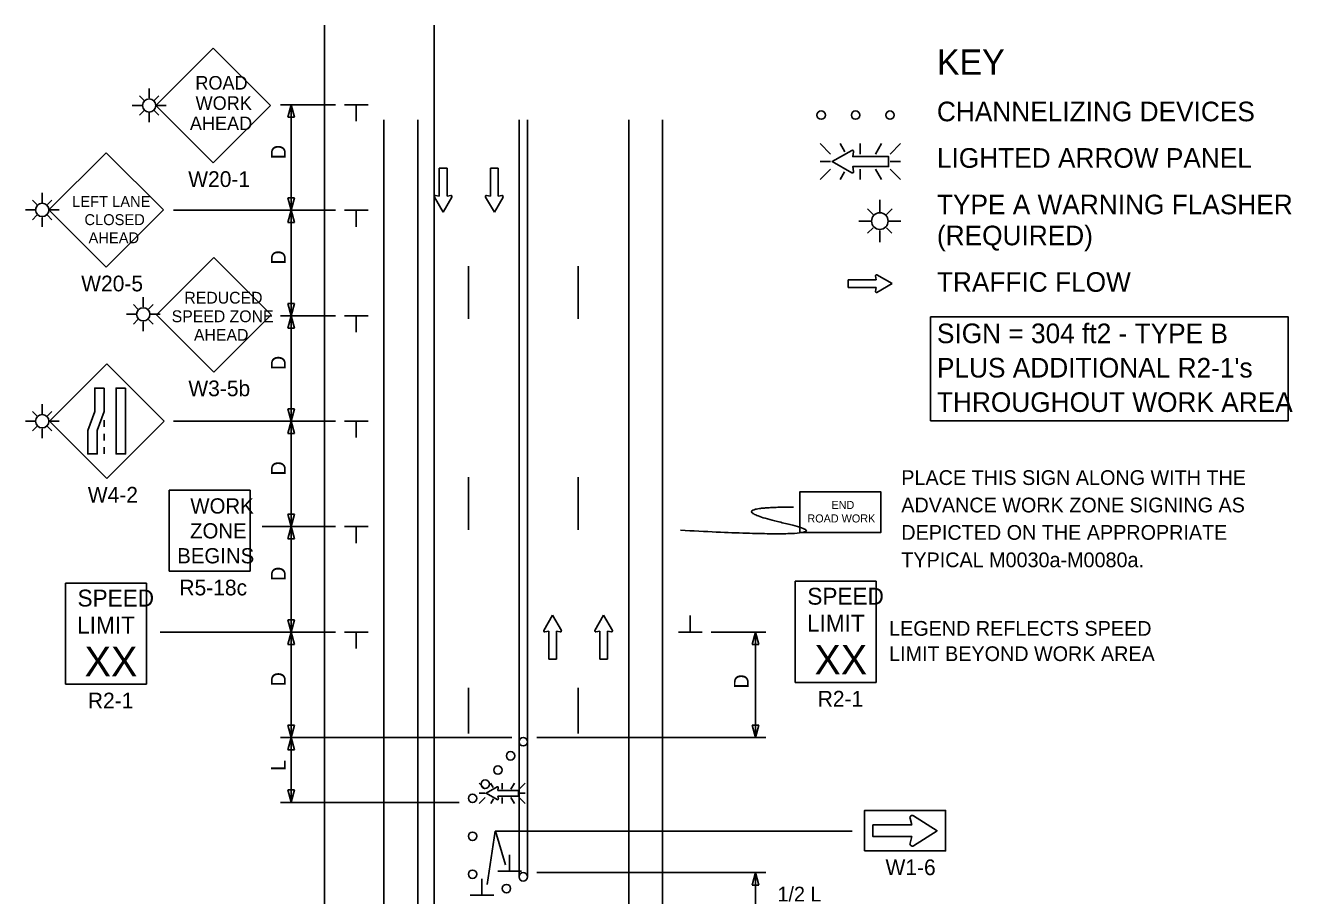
# Model space of a CAD drawing. Extents: x 16473 to 19504, y 4850 to 6919.
# Drawn here: x 16803 to 17404, y 6506 to 6919 of the extents above; entities that cross this region are included whole.
import ezdxf

# ---------------------------------------------------------------- set-up
doc = ezdxf.new("R2010")
doc.units = 0
for name, color, linetype in [('ALI_LEGAL_EX', 7, 'Continuous'), ('MT_SCRATCH_LEVEL_E', 7, 'Continuous'), ('PAVT_EDGE_EX', 7, 'Continuous'), ('TRAFFIC_SIGNS_PR', 7, 'Continuous'), ('TYPICAL_TEXT_DIMEN_EX', 7, 'Continuous'), ('TYPICAL_TEXT_DIMEN_PR', 7, 'Continuous')]:
    doc.layers.add(name, color=color, linetype=linetype)

msp = doc.modelspace()

# ---------------------------------------------------------------- linework, layer by layer
at = {"layer": 'ALI_LEGAL_EX'}
for p, q in [((16945.19, 6918.86), (16945.19, 6067.75)), ((16997.19, 6918.86), (16997.19, 6067.75))]:
    msp.add_line(p, q, dxfattribs=at)
for points in [[(17013.43, 6804.69), (17013.43, 6779.69)], [(17065.43, 6804.69), (17065.43, 6779.69)], [(17013.43, 6704.69), (17013.43, 6679.69)], [(17065.43, 6704.69), (17065.43, 6679.69)], [(17013.43, 6604.69), (17013.43, 6583.06)], [(17065.43, 6604.69), (17065.43, 6583.06)]]:
    msp.add_lwpolyline(points, dxfattribs=at)
at = {"layer": 'MT_SCRATCH_LEVEL_E'}
for p, q in [((17003.35, 6851.09), (16999.61, 6851.09)), ((16999.61, 6851.09), (16999.61, 6837.83)), ((17003.35, 6851.09), (16999.61, 6851.09)), ((16999.61, 6851.09), (16999.61, 6837.83)), ((17003.35, 6837.83), (17003.35, 6851.09)), ((17003.35, 6837.83), (17003.35, 6851.09)), ((17027.58, 6851.09), (17023.84, 6851.09)), ((17023.84, 6851.09), (17023.84, 6837.83)), ((17027.58, 6851.09), (17023.84, 6851.09)), ((17023.84, 6851.09), (17023.84, 6837.83)), ((17027.58, 6837.83), (17027.58, 6851.09)), ((17027.58, 6837.83), (17027.58, 6851.09)), ((16997.35, 6837.46), (17001.5, 6830.22)), ((16997.35, 6837.46), (17001.5, 6830.22)), ((16999.61, 6837.83), (16997.83, 6838.14)), ((16999.61, 6837.83), (16997.83, 6838.14)), ((17001.5, 6830.22), (17005.61, 6837.46)), ((17001.5, 6830.22), (17005.61, 6837.46)), ((17005.13, 6838.14), (17003.35, 6837.83)), ((17005.13, 6838.14), (17003.35, 6837.83)), ((17021.58, 6837.46), (17025.73, 6830.22)), ((17021.58, 6837.46), (17025.73, 6830.22)), ((17023.84, 6837.83), (17022.06, 6838.14)), ((17023.84, 6837.83), (17022.06, 6838.14)), ((17025.73, 6830.22), (17029.84, 6837.46)), ((17025.73, 6830.22), (17029.84, 6837.46)), ((17029.36, 6838.14), (17027.58, 6837.83)), ((17029.36, 6838.14), (17027.58, 6837.83)), ((17206.63, 6798.24), (17193.37, 6798.24)), ((17193.37, 6798.24), (17193.37, 6794.49)), ((17206.63, 6798.24), (17193.37, 6798.24)), ((17193.37, 6798.24), (17193.37, 6794.49)), ((17206.31, 6800.01), (17206.63, 6798.24)), ((17206.31, 6800.01), (17206.63, 6798.24)), ((17214.24, 6796.38), (17207, 6800.49)), ((17214.24, 6796.38), (17207, 6800.49)), ((17193.37, 6794.49), (17206.63, 6794.49)), ((17193.37, 6794.49), (17206.63, 6794.49)), ((17206.63, 6794.49), (17206.31, 6792.72)), ((17206.63, 6794.49), (17206.31, 6792.72)), ((17207, 6792.24), (17214.24, 6796.38)), ((17207, 6792.24), (17214.24, 6796.38)), ((17053.33, 6639.17), (17049.22, 6631.93)), ((17053.33, 6639.17), (17049.22, 6631.93)), ((17057.48, 6631.93), (17053.33, 6639.17)), ((17057.48, 6631.93), (17053.33, 6639.17)), ((17077.52, 6639.17), (17073.41, 6631.93)), ((17077.52, 6639.17), (17073.41, 6631.93)), ((17081.67, 6631.93), (17077.52, 6639.17)), ((17081.67, 6631.93), (17077.52, 6639.17)), ((17049.7, 6631.24), (17051.48, 6631.56)), ((17049.7, 6631.24), (17051.48, 6631.56)), ((17051.48, 6631.56), (17051.48, 6618.3)), ((17051.48, 6631.56), (17051.48, 6618.3)), ((17055.22, 6618.3), (17055.22, 6631.56)), ((17055.22, 6631.56), (17057, 6631.24)), ((17055.22, 6618.3), (17055.22, 6631.56)), ((17055.22, 6631.56), (17057, 6631.24)), ((17073.89, 6631.24), (17075.67, 6631.56)), ((17073.89, 6631.24), (17075.67, 6631.56)), ((17075.67, 6631.56), (17075.67, 6618.3)), ((17075.67, 6631.56), (17075.67, 6618.3)), ((17079.41, 6618.3), (17079.41, 6631.56)), ((17079.41, 6631.56), (17081.19, 6631.24)), ((17079.41, 6618.3), (17079.41, 6631.56)), ((17079.41, 6631.56), (17081.19, 6631.24)), ((17051.48, 6618.3), (17055.22, 6618.3)), ((17051.48, 6618.3), (17055.22, 6618.3)), ((17075.67, 6618.3), (17079.41, 6618.3)), ((17075.67, 6618.3), (17079.41, 6618.3))]:
    msp.add_line(p, q, dxfattribs=at)
for centre, start, end in [((16997.76, 6837.68), 80.03619, 209.77312), ((16997.76, 6837.68), 80.03619, 209.77312), ((17005.2, 6837.68), 330.42484, 99.96381), ((17005.2, 6837.68), 330.42484, 99.96381), ((17021.99, 6837.68), 80.03619, 209.77312), ((17021.99, 6837.68), 80.03619, 209.77312), ((17029.43, 6837.68), 330.42484, 99.96381), ((17029.43, 6837.68), 330.42484, 99.96381), ((17206.77, 6800.09), 60.42484, 189.96381), ((17206.77, 6800.09), 60.42484, 189.96381), ((17206.77, 6792.65), 170.03619, 299.77312), ((17206.77, 6792.65), 170.03619, 299.77312), ((17049.63, 6631.7), 150.42484, 279.96381), ((17049.63, 6631.7), 150.42484, 279.96381), ((17057.07, 6631.7), 260.03619, 29.77312), ((17057.07, 6631.7), 260.03619, 29.77312), ((17073.82, 6631.7), 150.42484, 279.96381), ((17073.82, 6631.7), 150.42484, 279.96381), ((17081.26, 6631.7), 260.03619, 29.77312), ((17081.26, 6631.7), 260.03619, 29.77312)]:
    msp.add_arc(centre, 0.463, start, end, dxfattribs=at)
at = {"layer": 'PAVT_EDGE_EX'}
for p, q in [((16973.43, 6873.99), (16973.43, 6149.2)), ((16989.43, 6873.99), (16989.43, 6149.2)), ((17037.43, 6873.99), (17037.43, 6514.86)), ((17041.43, 6873.99), (17041.43, 6515.67)), ((17089.43, 6873.99), (17089.43, 6149.2)), ((17105.43, 6873.99), (17105.43, 6149.2))]:
    msp.add_line(p, q, dxfattribs=at)
at = {"layer": 'TRAFFIC_SIGNS_PR'}
for p, q in [((16892.52, 6908.05), (16865.33, 6880.86)), ((16919.7, 6880.86), (16892.52, 6908.05)), ((16862.18, 6884.41), (16862.18, 6888.91)), ((16859.66, 6883.37), (16857.56, 6885.48)), ((16864.69, 6883.37), (16866.8, 6885.48)), ((16859.02, 6880.86), (16854.19, 6880.86)), ((16859.66, 6878.35), (16857.56, 6876.24)), ((16862.18, 6872.89), (16862.18, 6877.3)), ((16864.69, 6878.35), (16866.8, 6876.24)), ((16865.33, 6880.86), (16870.21, 6880.86)), ((16865.33, 6880.86), (16892.52, 6853.67)), ((16892.52, 6853.67), (16919.7, 6880.86)), ((16841.8, 6858.48), (16814.64, 6831.32)), ((16868.95, 6831.32), (16841.8, 6858.48)), ((17180.05, 6862.77), (17184.98, 6857.84)), ((17191.81, 6858.95), (17189.6, 6862.77)), ((17199.13, 6857.84), (17199.13, 6862.77)), ((17206.37, 6857.84), (17209.22, 6862.77)), ((17213.28, 6857.84), (17218.22, 6862.77)), ((17184.98, 6854.28), (17180.05, 6854.28)), ((17213.28, 6854.28), (17218.22, 6854.28)), ((17180.05, 6845.79), (17184.98, 6850.72)), ((17189.56, 6845.79), (17191.67, 6849.45)), ((17199.13, 6850.72), (17199.13, 6845.79)), ((17209.26, 6845.79), (17206.41, 6850.72)), ((17213.28, 6850.72), (17218.22, 6845.79)), ((16808.98, 6833.84), (16806.87, 6835.94)), ((16811.49, 6834.88), (16811.49, 6839.38)), ((16814, 6833.84), (16816.11, 6835.94)), ((17208.39, 6830.49), (17208.39, 6836.11)), ((16808.34, 6831.32), (16803.5, 6831.32)), ((16808.98, 6828.81), (16806.87, 6826.7)), ((16814, 6828.81), (16816.11, 6826.7)), ((16814.64, 6831.32), (16819.53, 6831.32)), ((16814.64, 6831.32), (16841.8, 6804.17)), ((16841.8, 6804.17), (16868.95, 6831.32)), ((17205.25, 6829.19), (17202.62, 6831.82)), ((17211.52, 6829.19), (17214.16, 6831.82)), ((16811.49, 6823.36), (16811.49, 6827.77)), ((17204.45, 6826.05), (17198.41, 6826.05)), ((17205.25, 6822.91), (17202.62, 6820.28)), ((17211.52, 6822.91), (17214.15, 6820.28)), ((17212.32, 6826.05), (17218.42, 6826.05)), ((17208.39, 6816.1), (17208.39, 6821.61)), ((16892.79, 6808.76), (16865.64, 6781.6)), ((16919.94, 6781.6), (16892.79, 6808.76)), ((16856.86, 6784.35), (16854.76, 6786.46)), ((16859.38, 6785.4), (16859.38, 6789.9)), ((16861.89, 6784.35), (16864, 6786.46)), ((16856.22, 6781.84), (16851.39, 6781.84)), ((16862.53, 6781.84), (16867.41, 6781.84)), ((16865.64, 6781.6), (16892.79, 6754.45)), ((16892.79, 6754.45), (16919.94, 6781.6)), ((16856.86, 6779.33), (16854.76, 6777.22)), ((16859.38, 6773.87), (16859.38, 6778.29)), ((16861.89, 6779.33), (16864, 6777.22)), ((16842.14, 6758.31), (16814.98, 6731.16)), ((16869.29, 6731.16), (16842.14, 6758.31)), ((16811.49, 6734.71), (16811.49, 6739.21)), ((16808.98, 6733.66), (16806.87, 6735.77)), ((16814, 6733.66), (16816.11, 6735.77)), ((16808.34, 6731.15), (16803.5, 6731.15)), ((16808.97, 6728.64), (16806.87, 6726.53)), ((16811.49, 6723.19), (16811.49, 6727.6)), ((16814, 6728.64), (16816.11, 6726.53)), ((16814.64, 6731.15), (16819.53, 6731.15)), ((16814.98, 6731.16), (16842.14, 6704.01)), ((16840.89, 6731.65), (16840.89, 6728.45)), ((16842.14, 6704.01), (16869.29, 6731.16)), ((16840.89, 6725.25), (16840.89, 6722.05)), ((16840.89, 6718.85), (16840.89, 6715.65)), ((16871.68, 6660.01), (16871.68, 6698.41)), ((16871.68, 6698.41), (16910.08, 6698.41)), ((16910.08, 6660.01), (16910.08, 6698.41)), ((16871.68, 6660.01), (16910.08, 6660.01)), ((16822.45, 6654.44), (16860.85, 6654.44)), ((16822.45, 6606.44), (16822.45, 6654.44)), ((16860.85, 6606.44), (16860.85, 6654.44)), ((17168.28, 6655.31), (17206.68, 6655.31)), ((17168.28, 6607.31), (17168.28, 6655.31)), ((17206.68, 6607.31), (17206.68, 6655.31)), ((16822.45, 6606.44), (16860.85, 6606.44)), ((17168.28, 6607.31), (17206.68, 6607.31)), ((17018.55, 6559.58), (17021.37, 6556.76)), ((17023.98, 6559.58), (17025.19, 6557.49)), ((17029.45, 6556.76), (17029.45, 6559.58)), ((17035.24, 6559.58), (17033.61, 6556.76)), ((17037.54, 6556.76), (17040.36, 6559.58)), ((17021.37, 6554.73), (17018.55, 6554.73)), ((17018.55, 6549.88), (17021.37, 6552.7)), ((17025.27, 6552.06), (17024.01, 6549.88)), ((17029.45, 6552.7), (17029.45, 6549.88)), ((17033.59, 6552.7), (17035.21, 6549.88)), ((17037.54, 6554.73), (17040.36, 6554.73)), ((17037.54, 6552.7), (17040.36, 6549.88)), ((17205.15, 6539.78), (17223.55, 6539.78)), ((17205.15, 6539.78), (17205.15, 6534.18)), ((17223.55, 6539.78), (17222.71, 6542.84)), ((17224.39, 6544.08), (17235.55, 6536.98)), ((17223.55, 6534.18), (17205.15, 6534.18)), ((17222.71, 6531.12), (17223.55, 6534.18)), ((17235.55, 6536.98), (17224.39, 6529.88))]:
    msp.add_line(p, q, dxfattribs=at)
for points in [[(17195.06, 6859.56), (17185.77, 6854.28), (17195.06, 6848.96)], [(17195.93, 6849.59), (17195.53, 6851.85), (17212.55, 6851.85), (17212.55, 6856.65), (17195.53, 6856.65), (17195.94, 6858.94)], [(17027.12, 6551.72), (17021.81, 6554.73), (17027.12, 6557.77)], [(17027.62, 6557.41), (17027.4, 6556.12), (17037.12, 6556.12), (17037.12, 6553.37), (17027.4, 6553.37), (17027.63, 6552.07)], [(17222.71, 6542.84), (17223.55, 6539.78), (17205.15, 6539.78), (17205.15, 6534.18), (17223.55, 6534.18), (17222.71, 6531.12)], [(17224.39, 6529.88), (17235.55, 6536.98), (17224.39, 6544.08)]]:
    msp.add_lwpolyline(points, dxfattribs=at)
for points in [[(16840.89, 6746.9), (16840.89, 6735.72), (16837.54, 6726.83), (16837.54, 6715.65), (16833.05, 6715.65), (16833.05, 6726.83), (16836.39, 6735.72), (16836.39, 6746.9)], [(16851.02, 6746.9), (16851.02, 6715.65), (16846.53, 6715.65), (16846.53, 6746.9)], [(17170.47, 6678.4), (17208.87, 6678.4), (17208.87, 6697.6), (17170.47, 6697.6)], [(17201.15, 6527.38), (17239.55, 6527.38), (17239.55, 6546.58), (17201.15, 6546.58)]]:
    msp.add_lwpolyline(points, close=True, dxfattribs=at)
for centre, radius in [((16862.18, 6880.86), 3.15), ((17180.61, 6876.31), 2), ((17196.91, 6876.31), 2), ((17213.21, 6876.31), 2), ((16811.49, 6831.32), 3.15), ((17208.39, 6826.05), 3.94), ((16859.38, 6781.84), 3.15), ((16811.49, 6731.15), 3.15), ((17039.43, 6579.2), 2), ((17033.43, 6572.48), 2), ((17027.43, 6565.77), 2), ((17021.43, 6559.06), 2), ((17015.43, 6552.35), 2), ((17015.43, 6534.35), 2), ((17015.43, 6534.35), 2), ((17015.43, 6516.35), 2), ((17039.43, 6515.11), 2), ((17031.43, 6509.53), 2)]:
    msp.add_circle(centre, radius, dxfattribs=at)
for centre, radius, start, end in [((17195.35, 6859.03), 0.598, 350.73078, 118.89165), ((17195.34, 6849.48), 0.597, 241.48329, 9.95933), ((17027.29, 6557.47), 0.341, 350.04067, 118.51671), ((17027.29, 6552.02), 0.341, 241.10835, 9.26922), ((17223.79, 6543.14), 1.12, 57.53038, 195.32692), ((17223.79, 6543.14), 1.12, 57.53038, 195.32692), ((17223.79, 6530.82), 1.12, 164.67308, 302.46962), ((17223.79, 6530.82), 1.12, 164.67308, 302.46963)]:
    msp.add_arc(centre, radius, start, end, dxfattribs=at)
msp.add_open_spline([(17167.51, 6690.42), (17129.72, 6690.42), (17197.74, 6674.95), (17113.94, 6679.44)], degree=2, dxfattribs=at)
at = {"layer": 'TYPICAL_TEXT_DIMEN_EX'}
msp.add_lwpolyline([(17232.44, 6780.57), (17401.89, 6780.57), (17401.89, 6731.37), (17232.44, 6731.37)], close=True, dxfattribs=at)
at = {"layer": 'TYPICAL_TEXT_DIMEN_PR'}
for p, q in [((16924.43, 6881.18), (16950.43, 6881.18)), ((16927.86, 6875.32), (16929.43, 6881.18)), ((16929.43, 6831.18), (16929.43, 6881.18)), ((16929.43, 6881.18), (16931, 6875.32)), ((16954.68, 6881.18), (16965.93, 6881.18)), ((16960.31, 6881.18), (16960.31, 6873.39)), ((16929.43, 6875.32), (16927.86, 6875.32)), ((16931, 6875.32), (16929.43, 6875.32)), ((16929.43, 6831.18), (16927.86, 6837.04)), ((16927.86, 6837.04), (16929.43, 6837.04)), ((16929.43, 6837.04), (16931, 6837.04)), ((16931, 6837.04), (16929.43, 6831.18)), ((16873.63, 6831.18), (16950.43, 6831.18)), ((16924.43, 6831.18), (16950.43, 6831.18)), ((16927.86, 6825.32), (16929.43, 6831.18)), ((16929.43, 6781.18), (16929.43, 6831.18)), ((16929.43, 6831.18), (16931, 6825.32)), ((16954.68, 6831.18), (16965.93, 6831.18)), ((16960.31, 6831.18), (16960.31, 6823.39)), ((16929.43, 6825.32), (16927.86, 6825.32)), ((16931, 6825.32), (16929.43, 6825.32)), ((16929.43, 6781.18), (16927.86, 6787.04)), ((16927.86, 6787.04), (16929.43, 6787.04)), ((16929.43, 6787.04), (16931, 6787.04)), ((16931, 6787.04), (16929.43, 6781.18)), ((16924.43, 6781.18), (16950.43, 6781.18)), ((16924.43, 6781.18), (16950.43, 6781.18)), ((16927.86, 6775.32), (16929.43, 6781.18)), ((16929.43, 6781.18), (16931, 6775.32)), ((16929.43, 6731.18), (16929.43, 6781.18)), ((16954.68, 6781.18), (16965.93, 6781.18)), ((16960.31, 6781.18), (16960.31, 6773.39)), ((16929.43, 6775.32), (16927.86, 6775.32)), ((16931, 6775.32), (16929.43, 6775.32)), ((16929.43, 6731.18), (16927.86, 6737.04)), ((16927.86, 6737.04), (16929.43, 6737.04)), ((16929.43, 6737.04), (16931, 6737.04)), ((16931, 6737.04), (16929.43, 6731.18)), ((16873.63, 6731.18), (16950.43, 6731.18)), ((16927.86, 6725.32), (16929.43, 6731.18)), ((16929.43, 6681.7), (16929.43, 6731.7)), ((16929.43, 6731.18), (16931, 6725.32)), ((16954.68, 6731.18), (16965.93, 6731.18)), ((16960.31, 6731.18), (16960.31, 6723.39)), ((16929.43, 6725.32), (16927.86, 6725.32)), ((16931, 6725.32), (16929.43, 6725.32)), ((16929.43, 6681.18), (16927.86, 6687.04)), ((16927.86, 6687.04), (16929.43, 6687.04)), ((16929.43, 6687.04), (16931, 6687.04)), ((16931, 6687.04), (16929.43, 6681.18)), ((16915.75, 6681.18), (16950.43, 6681.18)), ((16927.86, 6675.32), (16929.43, 6681.18)), ((16929.43, 6631.18), (16929.43, 6681.18)), ((16929.43, 6681.18), (16931, 6675.32)), ((16954.68, 6681.18), (16965.93, 6681.18)), ((16960.31, 6681.18), (16960.31, 6673.39)), ((16929.43, 6675.32), (16927.86, 6675.32)), ((16931, 6675.32), (16929.43, 6675.32)), ((16929.43, 6631.18), (16927.86, 6637.04)), ((16927.86, 6637.04), (16929.43, 6637.04)), ((16929.43, 6637.04), (16931, 6637.04)), ((16931, 6637.04), (16929.43, 6631.18)), ((17118.56, 6631.18), (17118.56, 6638.96)), ((16867.31, 6631.18), (16950.43, 6631.18)), ((16927.86, 6625.32), (16929.43, 6631.18)), ((16929.43, 6631.18), (16929.43, 6581.18)), ((16929.43, 6631.18), (16931, 6625.32)), ((16954.68, 6631.18), (16965.93, 6631.18)), ((16960.31, 6631.18), (16960.31, 6623.39)), ((17124.18, 6631.18), (17112.93, 6631.18)), ((17154.43, 6631.18), (17128.43, 6631.18)), ((17147.86, 6625.32), (17149.43, 6631.18)), ((17149.43, 6631.18), (17151, 6625.32)), ((17149.43, 6631.18), (17149.43, 6581.18)), ((16929.43, 6625.32), (16927.86, 6625.32)), ((16931, 6625.32), (16929.43, 6625.32)), ((17149.43, 6625.32), (17147.86, 6625.32)), ((17151, 6625.32), (17149.43, 6625.32)), ((16929.43, 6581.18), (16927.86, 6587.04)), ((16927.86, 6587.04), (16929.43, 6587.04)), ((16929.43, 6587.04), (16931, 6587.04)), ((16931, 6587.04), (16929.43, 6581.18)), ((17149.43, 6581.18), (17147.86, 6587.04)), ((17147.86, 6587.04), (17149.43, 6587.04)), ((17149.43, 6587.04), (17151, 6587.04)), ((17151, 6587.04), (17149.43, 6581.18)), ((17034.03, 6581.18), (16924.43, 6581.18)), ((16927.86, 6575.32), (16929.43, 6581.18)), ((16929.43, 6581.18), (16931, 6575.32)), ((16929.43, 6550.35), (16929.43, 6581.18)), ((17045.85, 6581.18), (17154.43, 6581.18)), ((16929.43, 6575.32), (16927.86, 6575.32)), ((16931, 6575.32), (16929.43, 6575.32)), ((16929.43, 6550.56), (16927.86, 6556.42)), ((16927.86, 6556.42), (16929.43, 6556.42)), ((16929.43, 6556.42), (16931, 6556.42)), ((16931, 6556.42), (16929.43, 6550.56)), ((17009.02, 6550.35), (16924.43, 6550.35)), ((17026.15, 6536.76), (17022.28, 6511.48)), ((17026.16, 6536.76), (17195.27, 6536.76)), ((17031.07, 6520.81), (17026.34, 6536.81)), ((17032.96, 6517.81), (17032.96, 6525.6)), ((17038.59, 6517.81), (17027.34, 6517.81)), ((17154.43, 6517.11), (17045.85, 6517.11)), ((17147.86, 6511.25), (17149.43, 6517.11)), ((17149.43, 6498.35), (17149.43, 6517.11)), ((17149.43, 6517.11), (17151, 6511.25)), ((17019.85, 6506.45), (17019.85, 6514.23)), ((17149.43, 6511.25), (17147.86, 6511.25)), ((17151, 6511.25), (17149.43, 6511.25)), ((17025.47, 6506.45), (17014.22, 6506.45))]:
    msp.add_line(p, q, dxfattribs=at)

# ---------------------------------------------------------------- texts
at = {"layer": 'TRAFFIC_SIGNS_PR'}
for s, height, p in [('ROAD', 6.408, (16884.05, 6888.4)), ('WORK', 6.408, (16884.16, 6878.79)), ('AHEAD', 6.408, (16881.46, 6869.18)), ('W20-1', 7.449, (16880.67, 6842.22)), ('LEFT LANE', 5.2, (16825.68, 6832.72)), ('CLOSED', 5.2, (16831.51, 6824.12)), ('AHEAD', 5.2, (16833.45, 6815.52)), ('W20-5', 7.44, (16829.97, 6792.73)), ('REDUCED', 5.6, (16878.85, 6786.91)), ('SPEED ZONE', 5.6, (16872.84, 6778.11)), ('AHEAD', 5.6, (16883.4, 6769.31)), ('W3-5b', 7.44, (16880.74, 6743.01)), ('PLACE THIS SIGN ALONG WITH THE', 7, (17218.57, 6700.92)), ('W4-2', 7.44, (16833.09, 6692.57)), ('WORK', 7.217, (16881.68, 6687.38)), ('END', 3.831, (17185.47, 6689.53)), ('ADVANCE WORK ZONE SIGNING AS', 7, (17218.57, 6687.92)), ('ROAD WORK', 3.831, (17174.08, 6683.15)), ('ZONE', 7.217, (16881.56, 6675.57)), ('DEPICTED ON THE APPROPRIATE', 7, (17218.57, 6674.92)), ('BEGINS', 7.217, (16875.48, 6663.76)), ('TYPICAL M0030a-M0080a.', 7, (17218.57, 6661.92)), ('R5-18c', 7.44, (16876.49, 6648.57)), ('SPEED', 8, (16828.22, 6643.3)), ('SPEED', 8, (17174.04, 6644.17)), ('LIMIT', 8, (16828.06, 6630.5)), ('LIMIT', 8, (17173.88, 6631.37)), ('XX', 14.031, (16831.56, 6610.2)), ('XX', 14.031, (17177.39, 6611.07)), ('R2-1', 7.44, (16833.13, 6595)), ('R2-1', 7.44, (17178.95, 6595.87)), ('W1-6', 7.44, (17211.09, 6515.94))]:
    msp.add_text(s, height=height, dxfattribs=at).set_placement(p)
at = {"layer": 'TYPICAL_TEXT_DIMEN_EX'}
for s, height, p in [('KEY', 12, (17235.45, 6895.42)), ('CHANNELIZING DEVICES', 9.3, (17235.45, 6873.37)), ('LIGHTED ARROW PANEL', 9.3, (17235.45, 6851.32)), ('TYPE A WARNING FLASHER', 9.3, (17235.45, 6829.27)), ('(REQUIRED)', 9.3, (17235.45, 6814.57)), ('TRAFFIC FLOW', 9.3, (17235.45, 6792.52)), ('SIGN = 304 ft2 - TYPE B', 9.3, (17235.45, 6768.16)), ("PLUS ADDITIONAL R2-1's", 9.3, (17235.45, 6751.86)), ('THROUGHOUT WORK AREA', 9.3, (17235.45, 6735.56))]:
    msp.add_text(s, height=height, dxfattribs=at).set_placement(p)
at = {"layer": 'TYPICAL_TEXT_DIMEN_PR'}
for s, p in [('D', (16926.87, 6855.4)), ('D', (16926.87, 6805.4)), ('D', (16926.87, 6755.4)), ('D', (16926.87, 6705.4)), ('D', (16926.87, 6655.4)), ('D', (16926.87, 6605.4)), ('D', (17146.24, 6604.39)), ('L', (16926.87, 6565.33))]:
    msp.add_text(s, height=7, rotation=90, dxfattribs=at).set_placement(p)
for s, p in [('LEGEND REFLECTS SPEED', (17212.8, 6629.42)), ('LIMIT BEYOND WORK AREA', (17212.8, 6617.42)), ('1/2 L', (17159.9, 6503.44))]:
    msp.add_text(s, height=7, dxfattribs=at).set_placement(p)

doc.saveas('drawing.dxf')
